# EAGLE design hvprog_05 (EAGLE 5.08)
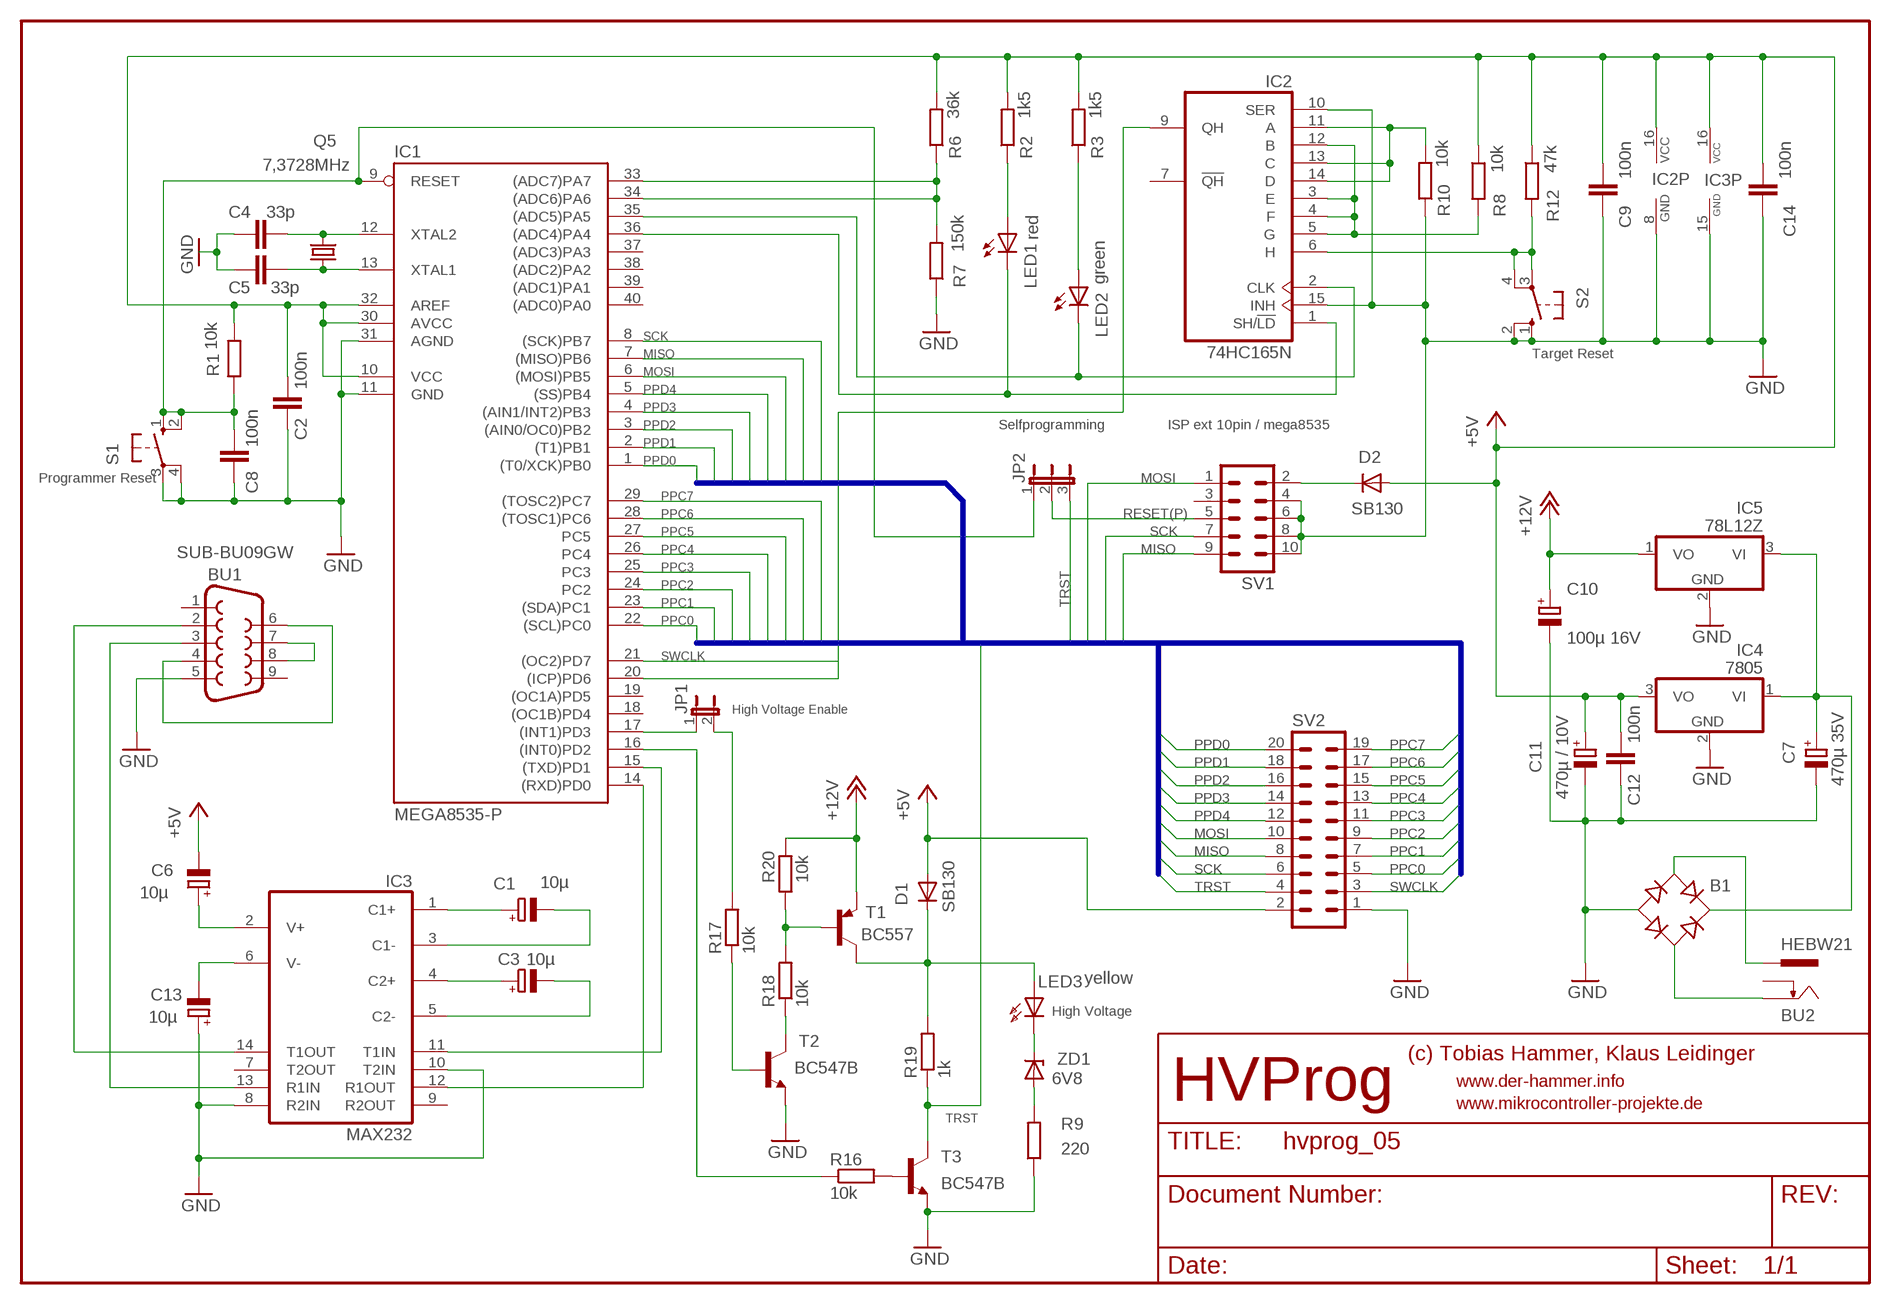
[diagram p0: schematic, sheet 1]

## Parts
B1  RB1A  [RB1A]
BU1  SUB-BU09GW  F09HP  [F09HP]
BU2  HEBW21  [HEBW21]
C1  10µ  CPOL-EUE1.8-4  [E1,8-4]
C2  100n  C-EU025-024X044  [C025-024X044]
C3  10µ  CPOL-EUE1.8-4  [E1,8-4]
C4  33p  C-EUC0805  [C0805]
C5  33p  C-EUC0805  [C0805]
C6  10µ  CPOL-EUE1.8-4  [E1,8-4]
C7  470µ 35V  CPOL-EUE5-10.5  [E5-10,5]
C8  100n  C-EU025-024X044  [C025-024X044]
C9  100n  C-EU025-024X044  [C025-024X044]
C10  100µ 16V  CPOL-EUE2.5-7  [E2,5-7]
C11  470µ / 10V  CPOL-EUE2.5-7  [E2,5-7]
C12  100n  C-EU025-024X044  [C025-024X044]
C13  10µ  CPOL-EUE1.8-4  [E1,8-4]
C14  100n  C-EU025-024X044  [C025-024X044]
D1  SB130  DIODE-D-2.5  [D-2.5]
D2  SB130  1N41485MM  [D-5]
IC1  MEGA8535-P  [DIL40]
IC2  74HC165N  [DIL16]
IC3  MAX232  [DIL16]
IC4  7805  78KL  [TO220H]
IC5  78L12Z  [TO92]
JP1  JP1E  [JP1]
JP2  JP2E  [JP2]
LED1  red  LED3MM  [LED3MM]
LED2  green  LED3MM  [LED3MM]
LED3  yellow  LED3MM  [LED3MM]
Q5  7,3728MHz  CRYTALHC49U-V  [HC49U-V]
R1  10k  R-EU_0204/7  [0204/7]
R2  1k5  R-EU_0204/7  [0204/7]
R3  1k5  R-EU_0204/7  [0204/7]
R6  36k  R-EU_0204/7  [0204/7]
R7  150k  R-EU_0204/7  [0204/7]
R8  10k  R-EU_0204/7  [0204/7]
R9  220  R-EU_0204/7  [0204/7]
R10  10k  R-EU_0204/7  [0204/7]
R12  47k  R-EU_0204/7  [0204/7]
R16  10k  R-EU_0204/7  [0204/7]
R17  10k  R-EU_0204/7  [0204/7]
R18  10k  R-EU_0204/7  [0204/7]
R19  1k  R-EU_0204/7  [0204/7]
R20  10k  R-EU_0204/7  [0204/7]
S1  10-XX  [B3F-10XX]
S2  10-XX  [B3F-10XX]
SV1  ML10L  [ML10L]
SV2  ML20L  [ML20L]
T1  BC557  [TO92]
T2  BC547B  [TO92]
T3  BC547B  [TO92]
ZD1  6V8  ZENER-DIODEZD-7.5  [ZDIO-7.5]

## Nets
+5V: C2.2 C6.- C9.1 C11.+ C12.1 C14.1 D1.A D2.A IC1.10(VCC) IC1.30(AVCC) IC1.32(AREF) IC2.16(VCC) IC3.16(VCC) IC4.3(VO) R1.2 R2.2 R3.2 R6.2 R8.1 R12.1 SV2.2
+12V: C10.+ IC5.1(VO) R20.2 T1.1(E)
GND: B1.- BU1.5 C2.1 C4.1 C5.1 C7.- C8.1 C9.2 C10.- C11.- C12.2 C13.+ C14.2 IC1.11(GND) IC1.31(AGND) IC2.8(GND) IC2.10(SER) IC2.15(INH) IC3.8(R2IN) IC3.10(T2IN) IC3.15(GND) IC4.2(GND) IC5.2(GND) R7.1 R9.1 R10.1 S1.3(P) S1.4(P1) S2.1(S) S2.2(S1) SV1.4 SV1.6 SV1.8 SV1.10 SV2.1 T2.1(E) T3.1(E)
MISO: IC1.7((MISO)PB6) SV1.9 SV2.8
MOSI: IC1.6((MOSI)PB5) SV1.1 SV2.10
N: IC1.36((ADC4)PA4) IC2.1(SH/!LD) LED1.K(C)
N$1: C4.2 IC1.12(XTAL2) Q5.2
N$2: C5.2 IC1.13(XTAL1) Q5.1
N$3: C8.2 IC1.9(RESET) JP2.1 R1.1 S1.1(S) S1.2(S1)
N$4: LED1.A R2.1
N$5: LED2.A R3.1
N$6: IC1.20((ICP)PD6) IC2.9(QH)
N$7: IC2.11(A) IC2.13(C) IC2.14(D) R10.2
N$8: IC1.35((ADC5)PA5) IC2.2(CLK) LED2.K(C)
N$9: IC1.33((ADC7)PA7) IC1.34((ADC6)PA6) R6.1 R7.2
N$10: BU1.7 BU1.8
N$11: IC1.16((INT0)PD2) R16.1
N$12: IC2.3(E) IC2.4(F) IC2.5(G) IC2.12(B) R8.2
N$13: R16.2 T3.2(B)
N$14: C1.+ IC3.1(C1+)
N$15: C1.- IC3.3(C1-)
N$16: C3.+ IC3.4(C2+)
N$17: C3.- IC3.5(C2-)
N$18: C13.- IC3.6(V-)
N$19: C6.+ IC3.2(V+)
N$20: IC2.6(H) R12.2 S2.3(P) S2.4(P1)
N$21: B1.+ C7.+ IC4.1(VI) IC5.3(VI)
N$22: B1.AC1 BU2.P$S(S)
N$23: B1.AC2 BU2.P$R(R)
N$24: LED3.K(C) ZD1.C
N$25: BU1.2 IC3.14(T1OUT)
N$26: BU1.3 IC3.13(R1IN)
N$27: IC1.14((RXD)PD0) IC3.12(R1OUT)
N$28: IC1.15((TXD)PD1) IC3.11(T1IN)
N$29: IC1.17((INT1)PD3) JP1.1
N$30: JP1.2 R17.2
N$31: R9.2 ZD1.A
N$32: BU1.4 BU1.6
N$33: D2.C SV1.2
N$34: D1.C LED3.A R19.2 T1.3(C)
N$35: R17.1 T2.2(B)
N$36: R18.1 T2.3(C)
N$38: R18.2 R20.1 T1.2(B)
PPC0: IC1.22((SCL)PC0) SV2.5
PPC1: IC1.23((SDA)PC1) SV2.7
PPC2: IC1.24(PC2) SV2.9
PPC3: IC1.25(PC3) SV2.11
PPC4: IC1.26(PC4) SV2.13
PPC5: IC1.27(PC5) SV2.15
PPC6: IC1.28((TOSC1)PC6) SV2.17
PPC7: IC1.29((TOSC2)PC7) SV2.19
PPD0: IC1.1((T0/XCK)PB0) SV2.20
PPD1: IC1.2((T1)PB1) SV2.18
PPD2: IC1.3((AIN0/OC0)PB2) SV2.16
PPD3: IC1.4((AIN1/INT2)PB3) SV2.14
PPD4: IC1.5((SS)PB4) SV2.12
RESET(P): JP2.2 SV1.5
SCK: IC1.8((SCK)PB7) SV1.7 SV2.6
SWCLK: IC1.21((OC2)PD7) SV2.3
TRST: JP2.3 R19.1 SV2.4 T3.3(C)
Unconnected: BU1.1 BU1.9 BU2.P$RS(RS) IC1.18((OC1B)PD4) IC1.19((OC1A)PD5) IC1.37((ADC3)PA3) IC1.38((ADC2)PA2) IC1.39((ADC1)PA1) IC1.40((ADC0)PA0) IC2.7(!QH) IC3.7(T2OUT) IC3.9(R2OUT) SV1.3

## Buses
B$2

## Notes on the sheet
- Target Reset
- Selfprogramming | ISP ext 10pin / mega8535
- Programmer Reset
- High Voltage Enable
- High Voltage
- (c) Tobias Hammer, Klaus Leidinger
- www.der-hammer.info
- HVProg
- www.mikrocontroller-projekte.de

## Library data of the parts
B1 = rectifier:RB1A: RECTIFIER 1 A
BU1 = con-subd:F09: SUB-D
BU2 = mikrocontroller-projekte:HEBW21: Hohlstecker Winkelbuchse Reichelt HEBW21/25
C1 C3 C6 = rcl:CPOL-EU: POLARIZED CAPACITOR, European symbol
C2 C4 C5 C8 C9 C14 = rcl:C-EU: CAPACITOR, European symbol
C7 C10 C11 C13 = rc-elektronik:CPOL-EU: POLARIZED CAPACITOR, European symbol
C12 = rc-elektronik:C-EU: CAPACITOR, European symbol
D1 = diode:DIODE-: DIODE
D2 = diode:1N4148: DIODE
IC1 = avr:MEGA8535-P: MICROCONTROLLER 8 Kbytes FLASH 512 bytes SRAM 512 bytes EEPROM USART 8-channel 10 bit ADC
IC2 = 74xx-eu:74*165: 8-bit parallel load SHIFT REGISTER
IC3 = maxim:MAX232: RS232 TRANSEIVER
IC4 IC5 = rc-elektronik:78*: Positive VOLTAGE REGULATOR
JP1 = jumper:JP1E: JUMPER
JP2 = jumper:JP2E: JUMPER
LED1 LED2 = led:LED: LED
LED3 = rc-elektronik:LED: LED
Q5 = crystal:CRYTAL: CRYSTAL
R1-R3 R6-R10 R12 R16-R20 = rcl:R-EU_: RESISTOR, European symbol
S1 S2 = switch-omron:10-XX: OMRON SWITCH
SV1 = con-harting-ml:ML10: HARTING
SV2 = con-harting-ml:ML20: HARTING
T1 = transistor-pnp:BC557: PNP Transistor
T2 T3 = transistor-npn:BC547*: NPN Transistor
ZD1 = diode:ZENER-DIODE: Z-Diode

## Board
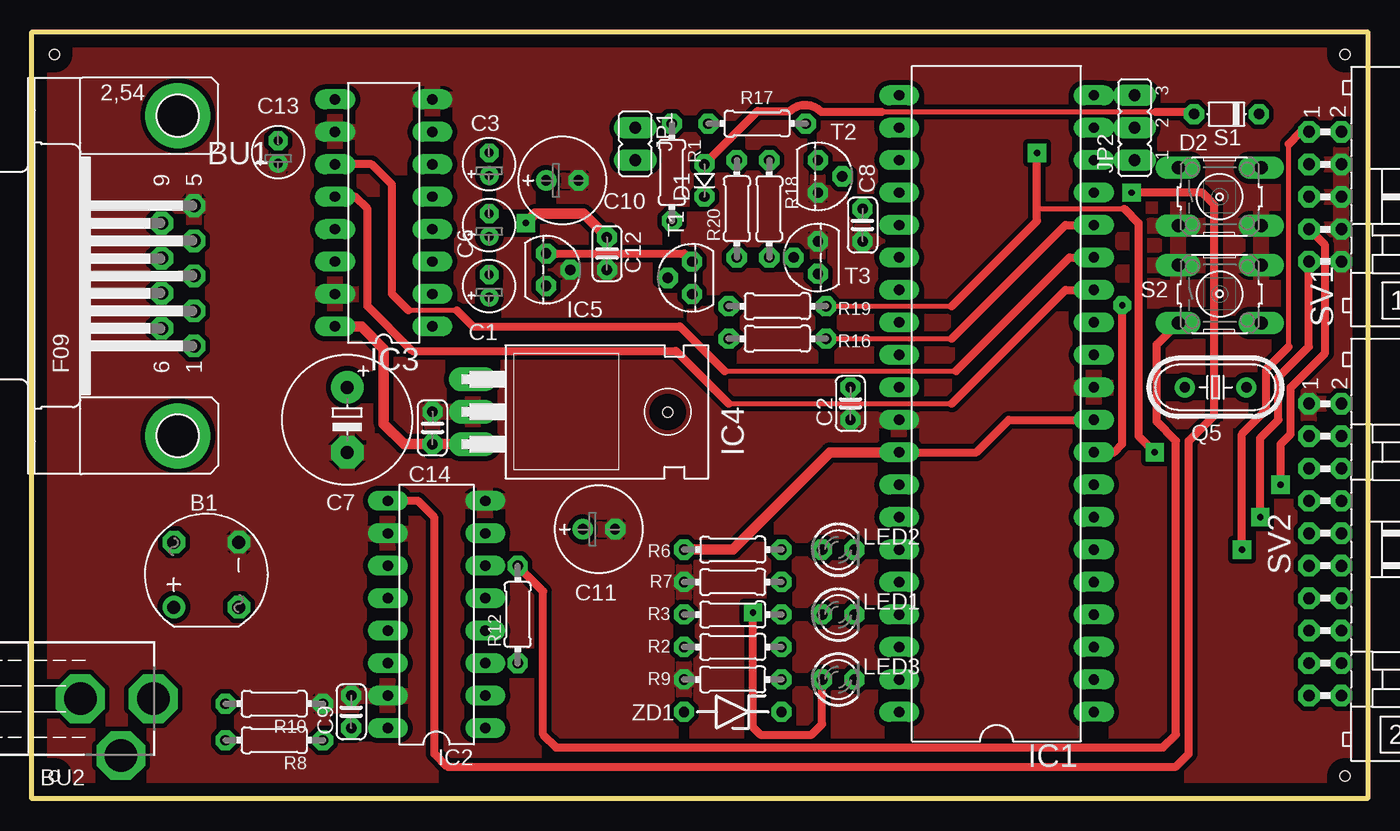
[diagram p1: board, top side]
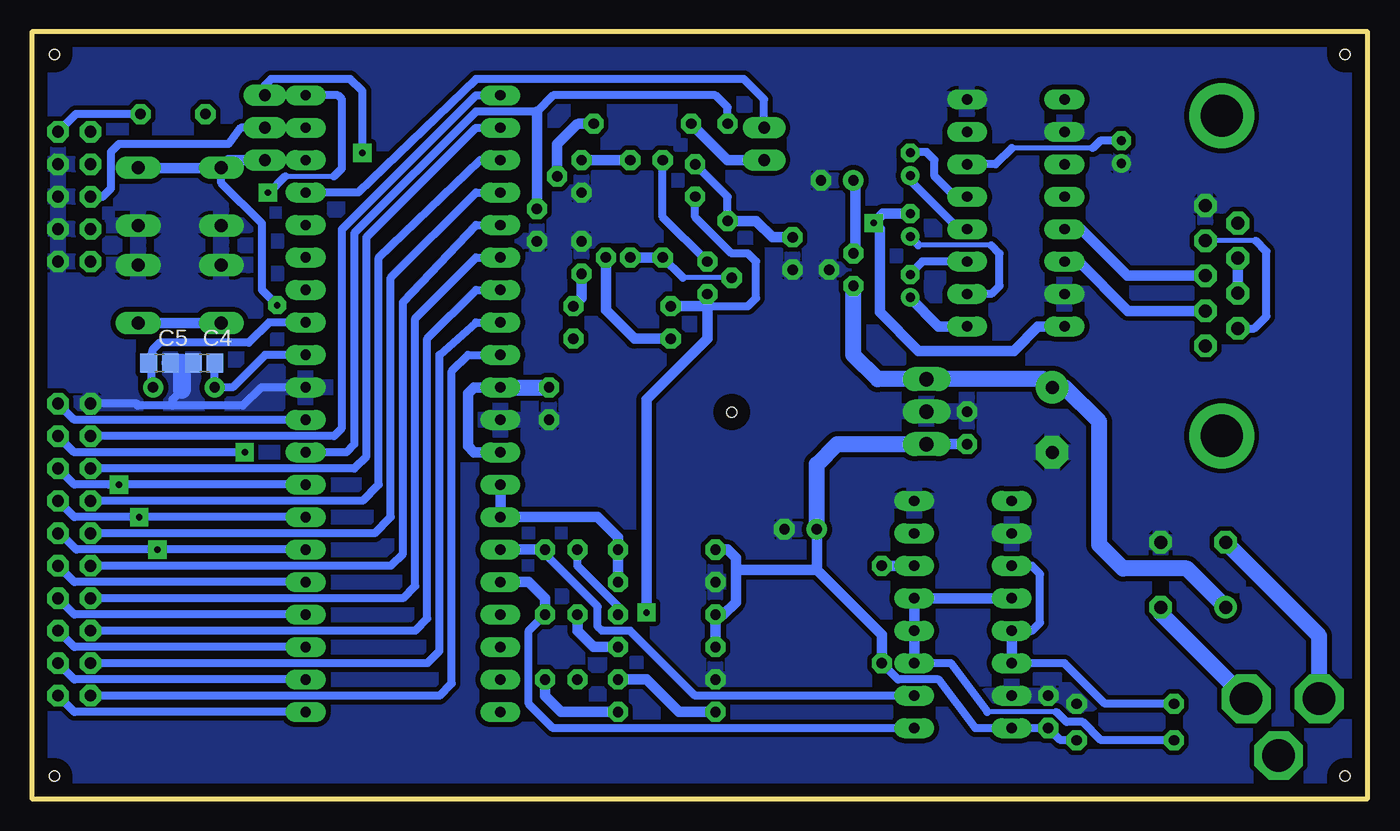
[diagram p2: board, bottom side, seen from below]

Size 104.5 x 60 mm. Coordinates in mm from the lower left corner, seen from the top.
Outline: 0,60 104.5,60 104.5,0 0,0 0,60
Copper layers (1*16): Top 0.035mm / dielectric 1.5mm / Bottom 0.035mm
Design rules "default *": minimum track width 10mil, minimum drill 5mil, track to track 15mil, track to pad 15mil, pad to pad 15mil, via to via 15mil, smd to smd 8mil, copper to edge 40mil, drill to drill 8mil, minimum pad ring 15mil, minimum via ring 8mil, stop-mask expansion 4mil, vias tented up to drill 0mil, thermal gap 10mil
Holes 0.8 mm at 49.75,30.25 102.75,1.75 1.75,1.75 1.75,58.25 102.75,58.25

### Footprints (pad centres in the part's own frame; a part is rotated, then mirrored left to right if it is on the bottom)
RB1A = drill 1.016 round: + -2.54,2.54 | drill 1.016 octagon: - 2.54,-2.54; AC1 2.54,2.54; AC2 -2.54,-2.54
F09HP = drill 1.016 octagon: 1 -5.486,-1.27; 2 -2.743,-1.27; 3 0,-1.27; 4 2.743,-1.27; 5 5.486,-1.27; 6 -4.115,1.27; 7 -1.372,1.27; 8 1.372,1.27; 9 4.115,1.27 | drill 3.302 pad 5.08 round: G1 -12.522,0; G2 12.522,0
HEBW21 = drill 2.54 pad 3.81 octagon: P$R 0,3.175; P$RS 4.445,0.635; P$S 0,-2.54
E1,8-4 = drill 0.711 pad 1.168 round: + -0.889,0 | drill 0.711 pad 1.168 octagon: - 0.889,0
C025-024X044 = drill 0.813 octagon: 1 -1.27,0; 2 1.27,0
C0805 = smd 1.3 x 1.5: 1 -0.85,0; 2 0.85,0
E5-10,5 = drill 1.016 pad 2.54 round: + -2.54,0 | drill 1.016 pad 2.54 octagon: - 2.54,0
E2,5-7 = drill 0.813 pad 1.6 round: + -1.27,0 | drill 0.813 pad 1.6 octagon: - 1.27,0
D-2.5 = drill 0.813 octagon: A 1.27,0; C -1.27,0
D-5 = drill 0.813 octagon: A 2.54,0; C -2.54,0
DIL40 = drill 0.813 long: 1 -24.13,-7.62; 2 -21.59,-7.62; 3 -19.05,-7.62; 4 -16.51,-7.62; 5 -13.97,-7.62; 6 -11.43,-7.62; 7 -8.89,-7.62; 8 -6.35,-7.62; 9 -3.81,-7.62; 10 -1.27,-7.62; 11 1.27,-7.62; 12 3.81,-7.62; 13 6.35,-7.62; 14 8.89,-7.62; 15 11.43,-7.62; 16 13.97,-7.62; 17 16.51,-7.62; 18 19.05,-7.62; 19 21.59,-7.62; 20 24.13,-7.62; 21 24.13,7.62; 22 21.59,7.62; 23 19.05,7.62; 24 16.51,7.62; 25 13.97,7.62; 26 11.43,7.62; 27 8.89,7.62; 28 6.35,7.62; 29 3.81,7.62; 30 1.27,7.62; 31 -1.27,7.62; 32 -3.81,7.62; 33 -6.35,7.62; 34 -8.89,7.62; 35 -11.43,7.62; 36 -13.97,7.62; 37 -16.51,7.62; 38 -19.05,7.62; 39 -21.59,7.62; 40 -24.13,7.62
DIL16 = drill 0.813 long: 1 -8.89,-3.81; 2 -6.35,-3.81; 3 -3.81,-3.81; 4 -1.27,-3.81; 5 1.27,-3.81; 6 3.81,-3.81; 7 6.35,-3.81; 8 8.89,-3.81; 9 8.89,3.81; 10 6.35,3.81; 11 3.81,3.81; 12 1.27,3.81; 13 -1.27,3.81; 14 -3.81,3.81; 15 -6.35,3.81; 16 -8.89,3.81
TO220H = drill 1.118 long: 1 -2.54,-10.16; 2 0,-10.16; 3 2.54,-10.16
TO92 = drill 0.813 octagon: 1 -1.27,0; 2 0,1.905; 3 1.27,0
JP1 = drill 0.914 long: 1 0,-1.27; 2 0,1.27
JP2 = drill 0.914 long: 1 -2.54,0; 2 0,0; 3 2.54,0
LED3MM = drill 0.813 octagon: A -1.27,0; K 1.27,0
HC49U-V = drill 0.813 round: 1 -2.413,0; 2 2.413,0
0204/7 = drill 0.813 octagon: 1 -3.81,0; 2 3.81,0
B3F-10XX = drill 1.016 long: 1 -3.251,2.261; 2 3.251,2.261; 3 -3.251,-2.261; 4 3.251,-2.261
ML10L = drill 0.914 octagon: 1 -5.08,-1.27; 2 -5.08,1.27; 3 -2.54,-1.27; 4 -2.54,1.27; 5 0,-1.27; 6 0,1.27; 7 2.54,-1.27; 8 2.54,1.27; 9 5.08,-1.27; 10 5.08,1.27
ML20L = drill 0.914 octagon: 1 -11.43,-1.27; 2 -11.43,1.27; 3 -8.89,-1.27; 4 -8.89,1.27; 5 -6.35,-1.27; 6 -6.35,1.27; 7 -3.81,-1.27; 8 -3.81,1.27; 9 -1.27,-1.27; 10 -1.27,1.27; 11 1.27,-1.27; 12 1.27,1.27; 13 3.81,-1.27; 14 3.81,1.27; 15 6.35,-1.27; 16 6.35,1.27; 17 8.89,-1.27; 18 8.89,1.27; 19 11.43,-1.27; 20 11.43,1.27
TO92' = drill 0.813 octagon: 1 1.27,0; 2 0,1.905; 3 -1.27,0
ZDIO-7.5 = drill 0.813 octagon: A 3.81,0; C -3.81,0

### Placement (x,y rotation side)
B1  13.64,17.52 90 top
BU1  11.41,40.92 90 top
BU2  6.32,7.81 270 top
C1  35.78,40.12 90 top
C2  64.04,30.92 90 top
C3  35.78,49.65 90 top
C4  91.03,34.09 0 bottom
C5  94.52,34.09 180 bottom
C6  35.78,44.89 90 top
C7  24.67,29.65 270 top
C8  64.99,44.89 90 top
C9  24.99,6.79 90 top
C10  41.5,48.38 0 top
C11  44.35,21.07 0 top
C12  44.99,42.66 270 top
C13  19.27,50.6 90 top
C14  31.34,29.01 90 top
D1  52.61,48.38 90 top
D2  93.46,53.57 180 top
IC1  75.47,30.92 90 top
IC2  31.65,14.41 90 top
IC3  27.53,45.84 90 top
IC4  44.67,30.28 270 top
IC5  40.23,41.39 270 top
JP1  47.21,51.24 180 top
JP2  86.26,52.51 90 top
LED1  63.09,14.41 0 top
LED2  63.09,19.49 0 top
LED3  63.09,9.33 0 top
Q5  92.61,32.19 180 top
R1  50.07,49.01 270 top
R2  54.83,11.87 180 top
R3  54.83,14.41 180 top
R6  54.83,19.49 180 top
R7  54.83,16.95 0 top
R8  18.95,4.56 180 top
R9  54.83,9.33 0 top
R10  18.95,7.42 180 top
R12  38,14.41 90 top
R16  58.32,36 180 top
R17  56.74,52.82 180 top
R18  57.69,46.16 270 top
R19  58.32,38.54 180 top
R20  55.15,46.16 90 top
S1  92.93,47.11 0 top
S2  92.93,39.49 0 top
SV1  101.19,47.11 270 top
SV2  101.19,19.49 270 top
T1  BC557  [TO92']  51.66,40.76 90 top
T2  BC547B  [TO92']  61.5,48.7 270 top
T3  BC547B  [TO92']  61.5,42.35 90 top
ZD1  54.83,6.79 180 top

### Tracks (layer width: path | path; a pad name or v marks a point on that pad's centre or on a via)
+5V  (via drill 0.5 pad 1.42)
  Top 0.406: 66.5,53.75 87.92,53.75
  Top 0.61: IC1.10 76.42,29.65 73.88,27.11 IC1.32 | D1.A 56.78,53.82 59.32,53.82 arc-90 61.75,53.75 66.5,53.75 | D2.A 90.74,53.75 87.92,53.75
  Top 0.813: IC3.16 25.78,36.95 27.53,35.2 27.53,29.33 29.11,27.74 IC4.3 | C12.1 43.15,45.77 39.37,45.77 v38.64,45.05 | R6.2 54.83,19.49 62.45,27.11 IC1.32 | IC1.32 | IC4.3 | v38.64,45.05 | v38.64,45.05
  Bottom 0.61: R12.1 36.73,9.33 33.56,9.33 30.7,5.52 IC2.16 C9.1 24.03,4.56 R8.1 | IC1.10 101.19,29.65 SV2.2 | R1.2 50.07,47.11 D1.A
  Bottom 0.813: R2.2 R3.2 50.39,14.41 49.43,15.36 49.43,17.9 | 43.08,17.9 C11.+ | 43.08,17.9 49.43,17.9 | 49.43,17.9 49.43,18.85 50.07,19.49 R6.2 | R12.1 38,12.82 43.08,17.9 | C12.1 46.58,43.93 47.85,45.2 R1.2 | 23.56,36.95 | IC3.16 23.56,36.95 | 23.56,36.95 25.78,36.95 27.68,35.04 35.15,35.04 38.16,38.06 38.16,44.57 v38.64,45.05 | IC1.30 69.91,32.19 70.39,31.71 70.39,27.58 69.91,27.11 68.01,27.11 67.85,26.95 IC1.32 | IC4.3 34.67,27.74 | IC4.3 | C14.1 | IC4.3 C14.1 | v38.64,45.05 | C6.- 37.91,45.77 v38.64,45.05
  Bottom 1.27: IC1.30 C2.2 | IC4.3 41.5,27.74 43.08,26.15 C11.+
+12V
  Top 0.406: IC5.1
  Top 0.61: T1.1 51.02,42.66 IC5.1
  Bottom 0.61: T1.1 55.15,45.52 R20.2
  Bottom 0.813: 40.07,42.51 | IC5.1 40.07,42.51 | C10.+ 40.07,48.22 40.07,42.51
GND
  Bottom 0.61: SV2.1 96.25,30.92 96.25,30.75 93.5,30.75 | 93.5,30.75 88,30.75 86.56,32.19 IC1.11 | 92.75,32 93.5,31.25 93.5,30.75
  Bottom 0.813: 50.86,16.95 | C7.-
  Bottom 1.422: C5.1 92.75,34.09 92.75,32
  pour Bottom: 0,59.9 104.2,59.9 104.2,0 0,0
  pour Top: 104.7,0 0.5,0 0,59.9 104.2,59.9
MISO  (via drill 0.5 pad 1.42)
  Top 0.61: SV1.9 99.92,35.36 97.53,32.98 97.53,29.65 96.11,28.22 v96.11,22.03
  Bottom 0.406: IC1.7
  Bottom 0.61: IC1.7 v96.11,22.03 101.19,22.03 SV2.8
MOSI  (via drill 0.5 pad 1.42)
  Top 0.406: 98.33,35.36 98.33,51.24
  Top 0.61: SV1.1 99.28,52.19 98.33,51.24 | 98.33,35.36 96.58,33.62 96.58,30.44 94.68,28.54 v94.68,19.49
  Bottom 0.406: 102.3,20.76 SV2.10 | IC1.6
  Bottom 0.61: IC1.6 v94.68,19.49 101.03,19.49 102.3,20.76
N
  Bottom 0.61: IC2.1 63.72,5.52 65.63,7.42 65.63,13.14 LED1.K
  Bottom 0.813: IC1.36 65.63,16.95 64.36,15.68 LED1.K
N$1
  Bottom 0.406: C4.2 90.07,34.09 90.2,33.96
  Bottom 0.61: IC1.12 86.26,34.73 88.8,32.19 Q5.2 90.2,33.96
N$2
  Bottom 0.406: 95.15,32.19 Q5.1 | C5.2 95.15,34.09
  Bottom 0.61: IC1.13 85.95,37.27 87.53,35.68 94.52,35.68 95.05,35.15 C5.2 | 95.15,34.09 95.15,32.19
N$3  (via drill 0.5 pad 1.42)
  Top 0.61: v85.31,38.62 85.31,27.74 84.68,27.11 IC1.9
  Bottom 0.406: 89.76,49.33 89.72,49.37 S1.1 | 96.11,49.33 96.14,49.37 S1.2
  Bottom 0.61: IC1.9 79.91,27.11 79.28,27.74 79.28,44.25 69.75,53.78 64.99,53.78 63.72,55.05 51.02,55.05 50.07,54.09 R1.1 | v85.31,38.62 86.5,39.8 86.5,45 89.68,48.18 S1.1
  Bottom 0.813: JP2.1 89.12,49.97 89.72,49.37 | 89.76,49.33 96.11,49.33 | 64.99,53.78 C8.2
N$4
  Bottom 0.813: LED1.A 61.82,13.14 60.55,11.87 R2.1
N$5
  Bottom 0.61: LED2.A 61.82,18.22 58.64,15.04 R3.1
N$6  (via drill 0.5 pad 1.42)
  Top 0.61: IC2.9 30.2,23.3 31.5,22 31.5,3.5 32.5,2.5 89.5,2.5 90.5,3.5 90.5,28 92.5,30 92.5,46.5 91.57,47.43 v86.03,47.43
  Bottom 0.406: 84.68,48.7 80.87,48.7
  Bottom 0.61: IC1.20 80.55,55.05 80.23,54.73 80.23,49.33 80.87,48.7 | 84.68,48.7 85.95,47.43 v86.03,47.43
N$7
  Bottom 0.61: R10.2 20.54,7.42 23.72,10.6 IC2.14 | IC2.11 26.26,18.22 25.62,17.58 25.62,13.77 26.26,13.14 IC2.13
  Bottom 0.813: IC2.14 IC2.13
N$8
  Bottom 0.406: 64.36,19.17 LED2.K
  Bottom 0.61: 64.36,19.17 60.23,15.04 60.23,13.45 59.91,13.14 57.69,13.14 52.61,8.06 IC2.2
  Bottom 0.813: LED2.K IC1.35
N$9
  Bottom 0.406: R6.1 58.96,19.49
  Bottom 0.813: R7.2 R6.1 58.64,20.44 60.23,22.03 61.18,22.03 IC1.34 IC1.33
N$10
  Bottom 0.813: BU1.7 BU1.8
N$11
  Top 0.406: R16.1 71.98,36
  Top 0.61: 71.98,36 80.87,44.89 IC1.16
N$12
  Bottom 0.406: 24.35,6.79 29.75,6.79
  Bottom 0.61: R8.2 20.86,4.56 22.29,5.99 23.56,5.99 24.35,6.79 | 29.75,6.79 32.61,10.6 IC2.3
  Bottom 0.813: IC2.3 IC2.4 IC2.5 IC2.12
N$13
  Bottom 0.813: R16.2 57.37,36 59.59,38.22 T3.2
N$14
  Bottom 0.406: 35.78,39.17 C1.+
  Bottom 0.813: IC3.1 33.56,36.95 35.78,39.17
N$15
  Bottom 0.406: 35.78,41.08 C1.-
  Bottom 0.61: IC3.3 34.83,42.03 35.78,41.08
N$16
  Bottom 0.61: C3.+ 35.78,48.38 31.97,44.57 IC3.4
N$17
  Bottom 0.406: 35.46,50.6 35.53,50.54
  Bottom 0.61: IC3.5 32.29,47.11 33.88,48.7 33.88,49.97 34.51,50.6 35.46,50.6 | 35.53,50.54 C3.-
N$18
  Bottom 0.406: 21.49,50.92 27.84,50.92
  Bottom 0.61: C13.- 20.92,51.49 21.49,50.92 | 27.84,50.92 29.11,49.65 IC3.6
N$19
  Bottom 0.406: 35.78,43.93 C6.+ | 29.43,43.3 35.15,43.3
  Bottom 0.61: IC3.2 29.43,39.49 28.8,40.12 28.8,42.66 29.43,43.3 | 35.15,43.3 35.78,43.93
N$20
  Top 0.61: R12.2 40,16.22 40,5 41,4 88.5,4 89.5,5 89.5,28 88,29.5 88,35.55 S2.3
  Bottom 0.813: R12.2 IC2.6 | S2.4 96.14,37.23 96.11,37.27 96.07,37.23 S2.3
N$21
  Bottom 1.27: IC5.3 40.23,34.73 38.32,32.82 IC4.1 25.3,32.82 C7.+ 23.69,32.19 21,29.5 21,19.86 19.14,18 14.12,18 B1.+
N$22
  Bottom 1.27: BU2.P$S 3.78,12.73 B1.AC1
N$23
  Bottom 1.27: BU2.P$R 16.18,14.5 B1.AC2
N$24
  Bottom 0.813: ZD1.C 63.09,6.79 64.36,8.06 LED3.K | LED3.K
N$25
  Bottom 0.813: IC3.14 23.56,42.03 22.61,42.03 18.75,38.17 BU1.2
N$26
  Bottom 0.813: IC3.13 23.56,44.57 22.45,44.57 18.8,40.92 BU1.3
N$27
  Top 0.406: 54.51,30.92 71.98,30.92
  Top 0.61: 71.98,30.92 80.87,39.81 IC1.14 | 54.51,30.92 50.39,35.04 29.75,35.04 26.26,38.54 26.26,46.16 25.3,47.11 IC3.12
N$28
  Top 0.406: 54.2,33.46 72.29,33.46 | 29.43,38.22 33.24,38.22
  Top 0.61: 72.29,33.46 81.18,42.35 IC1.15 | 54.2,33.46 50.7,36.95 34.51,36.95 33.24,38.22 | 29.43,38.22 28.16,39.49 28.16,48.06 26.57,49.65 IC3.11
N$29
  Bottom 0.61: IC1.17 78.96,47.43 69.75,56.32 48.8,56.32 47.21,54.73 JP1.1
N$30
  Bottom 0.813: JP1.2 50.07,49.97 R17.2
N$31
  Bottom 0.813: ZD1.A 53.88,6.79 56.42,9.33 R9.2
N$32
  Bottom 0.406: 8.76,43.66 BU1.4 | 10.3,36.79 10.31,36.8 BU1.6
  Bottom 0.61: 8.76,43.66 7.92,42.82 7.92,37.74 8.87,36.79 10.3,36.79
N$33
  Bottom 0.61: D2.C 101.08,53.57 SV1.2
N$34  (via drill 0.5 pad 1.42)
  Top 0.61: v56.42,14.57 56.42,5.58 57,5 61,5 61.82,5.82 LED3.A
  Bottom 0.61: D1.C 52.61,45.52 49.75,42.66 48.48,42.66 47.85,42.03 47.85,39.17 48.48,38.54 51.66,38.54
  Bottom 0.813: 51.66,38.54 51.66,36 56.42,31.23 v56.42,14.57 | 51.66,38.54 T1.3 | 51.66,38.54 R19.2
N$35
  Bottom 0.406: 61.89,52.75 arc45 61.71,52.82
  Bottom 0.813: 61.71,52.82 R17.1 | 61.89,52.75 63.4,51.24 T2.2
N$36
  Bottom 0.813: R18.1 T2.3
N$38
  Bottom 0.406: T1.2 53.56,40.76
  Bottom 0.61: 53.56,40.76 R20.1
  Bottom 0.813: R20.1 R18.2
PPC0
  Bottom 0.61: IC1.22 69.75,52.51 78.33,43.93 78.33,26.79 79.28,25.84 SV2.5
PPC1
  Bottom 0.61: IC1.23 69.44,49.97 77.37,42.35 77.37,24.57 78.64,23.3 SV2.7
PPC2
  Bottom 0.61: IC1.24 69.75,47.43 76.42,40.76 76.42,22.03 77.69,20.76 SV2.9
PPC3
  Bottom 0.61: IC1.25 69.75,44.89 75.47,38.85 75.47,19.17 76.42,18.22 SV2.11
PPC4
  Bottom 0.61: IC1.26 69.75,42.35 74.52,37.58 74.52,16.63 75.47,15.68 SV2.13
PPC5
  Bottom 0.61: IC1.27 69.75,39.81 73.56,36 73.56,14.09 74.52,13.14 SV2.15
PPC6
  Bottom 0.61: IC1.28 69.75,37.27 72.61,34.73 72.61,11.55 73.56,10.6 SV2.17
PPC7
  Bottom 0.61: IC1.29 70.39,34.73 71.66,33.46 71.66,9.01 72.61,8.06 SV2.19
PPD0
  Bottom 0.61: IC1.1 101.19,6.79 SV2.20
PPD1
  Bottom 0.61: IC1.2 101.19,9.33 SV2.18
PPD2
  Bottom 0.61: IC1.3 101.19,11.87 SV2.16
PPD3
  Bottom 0.61: IC1.4 101.19,14.41 SV2.14
PPD4
  Bottom 0.61: IC1.5 101.19,16.95 SV2.12
RESET(P)
  Bottom 0.61: JP2.2 88.17,52.51 89.12,51.24 97.69,51.24 98.33,50.6 98.33,47.74 98.96,47.11 SV1.5
SCK  (via drill 0.5 pad 1.42)
  Top 0.61: SV1.7 101.19,43.3 101.19,34.88 98.49,32.19 98.49,28.54 97.69,27.74 v97.69,24.57
  Bottom 0.406: 98.49,24.57 v97.69,24.57 | SV2.6
  Bottom 0.61: v97.69,24.57 101.19,24.57 SV2.6 | IC1.8 98.49,24.57
SWCLK
  Bottom 0.61: IC1.21 69.75,55.05 80.23,44.57 80.23,29.01 80.87,28.38 SV2.3
TRST  (via drill 0.5 pad 1.42)
  Top 0.406: R19.1 71.98,38.54 | 78.64,46.16 85.47,46.16
  Top 0.61: 71.98,38.54 78.64,45.2 78.64,46.16 v78.64,50.53 | v87.85,27.11 86.58,28.38 86.58,45.05 85.47,46.16
  Bottom 0.61: SV2.4 101.19,27.11 v87.85,27.11 | v78.64,50.53 78.64,55.36 79.6,56.32 85.79,56.32 86.26,55.84 JP2.3
  Bottom 0.813: T3.3 61.5,39.17 R19.1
